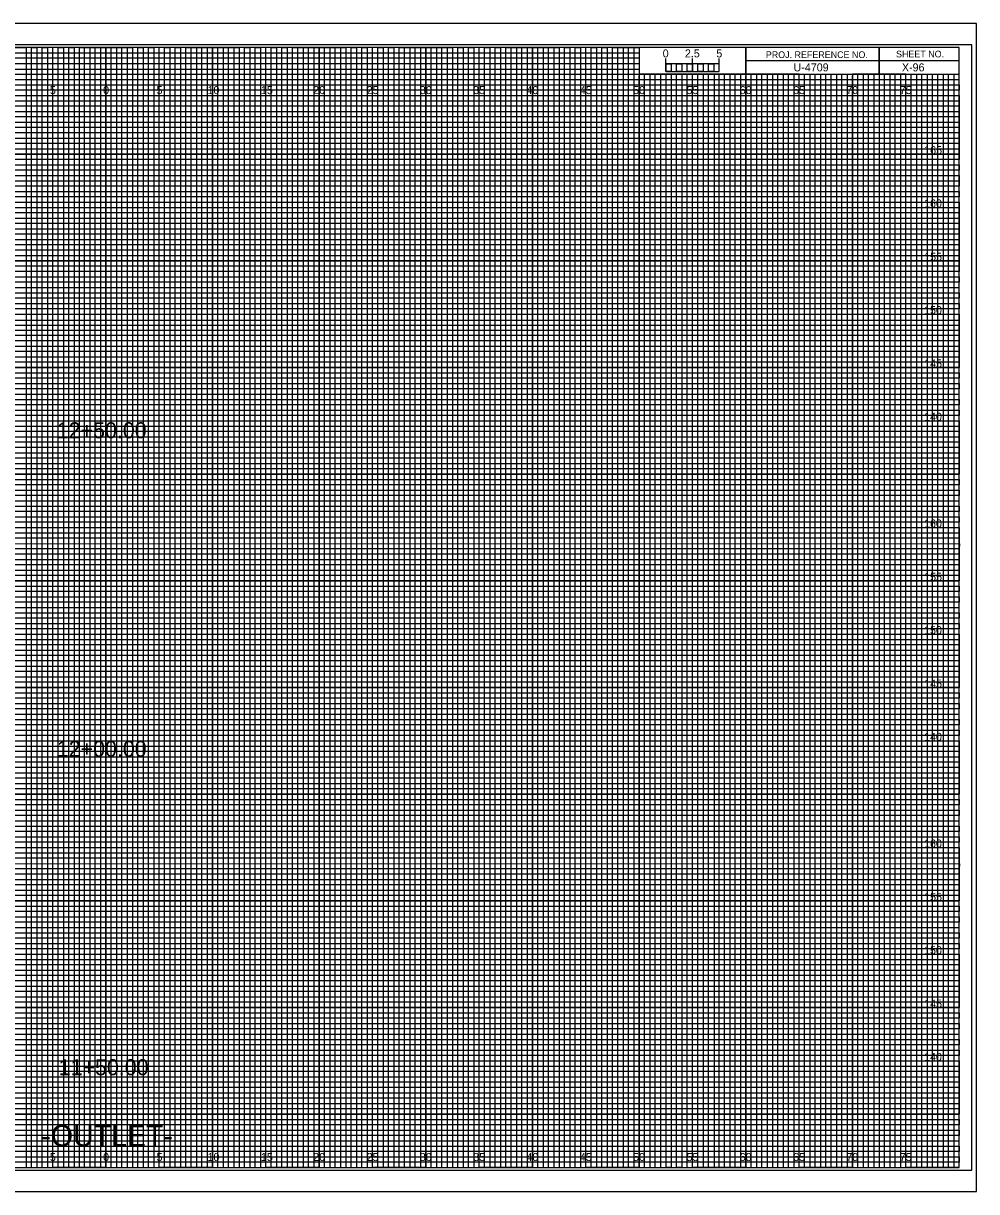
# Model space of a CAD drawing. Extents: x -7 to 162, y 108 to 217.
# Drawn here: x 72.2 to 161.7, y 107.7 to 217.2 of the extents above; entities that cross this region are included whole.
import ezdxf

# ---------------------------------------------------------------- set-up
doc = ezdxf.new("R2010")
doc.units = 0
for name, color, linetype in [('Exist CMT Pavement', 7, 'Continuous'), ('Exist Cross Section Cell', 7, 'Continuous'), ('Exist XS Center Line Elevation Label', 7, 'Continuous'), ('Exist XS Ground Line', 7, 'Continuous'), ('Prop CMT Concrete Structures', 7, 'Continuous'), ('Prop CMT Pvmt Course 1 CG', 7, 'Continuous'), ('Prop CMT Pvmt Course 1 Wedge', 7, 'Continuous'), ('Prop CMT Pvmt Course 2', 7, 'Continuous'), ('Prop CMT Pvmt Course 2 Wedge', 7, 'Continuous'), ('Prop CMT Pvmt Course 3', 7, 'Continuous'), ('Prop CMT Pvmt Course 3 Wedge', 7, 'Continuous'), ('Prop CMT Pvmt Surface', 7, 'Continuous'), ('Prop CMT Pvmt Wedge Surface 1', 7, 'Continuous'), ('Prop CMT Pvmt Wedge Surface 2', 7, 'Continuous'), ('Prop CMT Pvmt Wedge Surface 3', 7, 'Continuous'), ('Prop CMT Subgrade Earthwork', 7, 'Continuous'), ('Scratch_Level_0', 7, 'Continuous')]:
    doc.layers.add(name, color=color, linetype=linetype)

msp = doc.modelspace()

# ---------------------------------------------------------------- linework, layer by layer
at = {"layer": 'Exist XS Center Line Elevation Label'}
for points in [[(67.5, 215), (72.5, 215), (72.5, 110), (77.5, 110), (77.5, 215), (82.5, 215), (82.5, 110), (87.5, 110), (87.5, 215), (92.5, 215), (92.5, 110), (97.5, 110), (97.5, 215), (102.5, 215), (102.5, 110), (107.5, 110), (107.5, 215), (112.5, 215), (112.5, 110), (117.5, 110), (117.5, 215), (122.5, 215), (122.5, 110), (127.5, 110), (127.5, 215), (129.97, 215), (130, 215), (130, 212.5), (132.5, 212.5), (132.5, 110), (137.5, 110), (137.5, 212.5), (142.5, 212.5), (142.5, 110), (147.5, 110), (147.5, 212.5), (152.5, 212.5), (152.5, 110), (157.5, 110), (157.5, 212.5)], [(0, 212.5), (137.5, 212.5)], [(0, 202.5), (160, 202.5), (160, 207.5), (0, 207.5)], [(0, 192.5), (160, 192.5), (160, 197.5), (0, 197.5)], [(0, 182.5), (160, 182.5), (160, 187.5), (0, 187.5)], [(0, 172.5), (160, 172.5), (160, 177.5), (0, 177.5)], [(0, 162.5), (160, 162.5), (160, 167.5), (0, 167.5)], [(0, 152.5), (160, 152.5), (160, 157.5), (0, 157.5)], [(0, 142.5), (160, 142.5), (160, 147.5), (0, 147.5)], [(0, 132.5), (160, 132.5), (160, 137.5), (0, 137.5)], [(0, 122.5), (160, 122.5), (160, 127.5), (0, 127.5)], [(0, 112.5), (160, 112.5), (160, 117.5), (0, 117.5)]]:
    msp.add_lwpolyline(points, dxfattribs=at)
at = {"layer": 'Exist XS Ground Line'}
for p, q in [((75, 215), (70, 215)), ((75, 110), (75, 215)), ((85, 215), (80, 215)), ((80, 215), (80, 110)), ((85, 110), (85, 215)), ((95, 215), (90, 215)), ((90, 215), (90, 110)), ((95, 110), (95, 215)), ((105, 215), (100, 215)), ((100, 215), (100, 110)), ((105, 110), (105, 215)), ((115, 215), (110, 215)), ((110, 215), (110, 110)), ((115, 110), (115, 215)), ((125, 215), (120, 215)), ((120, 215), (120, 110)), ((125, 110), (125, 215)), ((130, 215), (130, 110)), ((135, 110), (135, 212.5)), ((145, 212.5), (140, 212.5)), ((140, 212.5), (140, 110)), ((145, 110), (145, 212.5)), ((155, 212.5), (150, 212.5)), ((150, 212.5), (150, 110)), ((155, 110), (155, 212.5)), ((80, 110), (75, 110)), ((90, 110), (85, 110)), ((100, 110), (95, 110)), ((110, 110), (105, 110)), ((120, 110), (115, 110)), ((130, 110), (125, 110)), ((140, 110), (135, 110)), ((150, 110), (145, 110)), ((160, 110), (155, 110)), ((160, 110), (160, 110))]:
    msp.add_line(p, q, dxfattribs=at)
for points in [[(0, 210), (160, 210), (160, 205), (0, 205)], [(0, 200), (160, 200), (160, 195), (0, 195)], [(0, 190), (160, 190), (160, 185), (0, 185)], [(0, 180), (160, 180), (160, 175), (0, 175)], [(0, 170), (160, 170), (160, 165), (0, 165)], [(0, 160), (160, 160), (160, 155), (0, 155)], [(0, 150), (160, 150), (160, 145), (0, 145)], [(0, 140), (160, 140), (160, 135), (0, 135)], [(0, 130), (160, 130), (160, 125), (0, 125)], [(0, 120), (160, 120), (160, 115), (0, 115)]]:
    msp.add_lwpolyline(points, dxfattribs=at)
at = {"layer": 'Prop CMT Concrete Structures'}
for p, q in [((161.65, 217.25), (-6.7, 217.25)), ((-6.7, 107.75), (161.65, 107.75))]:
    msp.add_line(p, q, dxfattribs=at)
at = {"layer": 'Prop CMT Pvmt Course 1 Wedge'}
msp.add_lwpolyline([(-6.7, 107.75), (161.65, 107.75), (161.65, 217.25), (-6.7, 217.25)], close=True, dxfattribs=at)
at = {"layer": 'Prop CMT Pvmt Course 2'}
for p, q in [((152.5, 215), (152.5, 212.5)), ((152.5, 212.5), (152.5, 215)), ((160, 213.75), (140, 213.75)), ((140, 213.75), (140, 212.5)), ((140, 212.5), (160, 212.5))]:
    msp.add_line(p, q, dxfattribs=at)
for points in [[(160, 215), (0, 215), (0, 110), (160, 110)], [(140, 215), (130, 215), (130, 212.52), (140, 212.52)], [(160, 215), (140, 215), (140, 212.5), (160, 212.5)]]:
    msp.add_lwpolyline(points, close=True, dxfattribs=at)
at = {"layer": 'Prop CMT Pvmt Course 2 Wedge'}
msp.add_lwpolyline([(-5.4, 109.75), (161.2, 109.75), (161.2, 215.25), (-5.4, 215.25)], close=True, dxfattribs=at)
at = {"layer": 'Prop CMT Pvmt Course 3'}
for p, q in [((133.5, 212.5), (133, 212.5)), ((133, 212.5), (133, 110)), ((133.5, 110), (133.5, 212.5)), ((134.5, 212.5), (134, 212.5)), ((134, 212.5), (134, 110)), ((134.5, 110), (134.5, 212.5)), ((133, 110), (132.5, 110)), ((134, 110), (133.5, 110))]:
    msp.add_line(p, q, dxfattribs=at)
for points in [[(72.5, 110), (73, 110), (73, 215), (73.5, 215), (73.5, 110)], [(73.5, 110), (74, 110), (74, 215), (74.5, 215), (74.5, 110)], [(75, 110), (75.5, 110), (75.5, 215), (76, 215), (76, 110)], [(76, 110), (76.5, 110), (76.5, 215), (77, 215), (77, 110)], [(77.5, 110), (78, 110), (78, 215), (78.5, 215), (78.5, 110)], [(78.5, 110), (79, 110), (79, 215), (79.5, 215), (79.5, 110)], [(80, 110), (80.5, 110), (80.5, 215), (81, 215), (81, 110)], [(81, 110), (81.5, 110), (81.5, 215), (82, 215), (82, 110)], [(82.5, 110), (83, 110), (83, 215), (83.5, 215), (83.5, 110)], [(83.5, 110), (84, 110), (84, 215), (84.5, 215), (84.5, 110)], [(85, 110), (85.5, 110), (85.5, 215), (86, 215), (86, 110)], [(86, 110), (86.5, 110), (86.5, 215), (87, 215), (87, 110)], [(87.5, 110), (88, 110), (88, 215), (88.5, 215), (88.5, 110)], [(88.5, 110), (89, 110), (89, 215), (89.5, 215), (89.5, 110)], [(90, 110), (90.5, 110), (90.5, 215), (91, 215), (91, 110)], [(91, 110), (91.5, 110), (91.5, 215), (92, 215), (92, 110)], [(92.5, 110), (93, 110), (93, 215), (93.5, 215), (93.5, 110)], [(93.5, 110), (94, 110), (94, 215), (94.5, 215), (94.5, 110)], [(95, 110), (95.5, 110), (95.5, 215), (96, 215), (96, 110)], [(96, 110), (96.5, 110), (96.5, 215), (97, 215), (97, 110)], [(97.5, 110), (98, 110), (98, 215), (98.5, 215), (98.5, 110)], [(98.5, 110), (99, 110), (99, 215), (99.5, 215), (99.5, 110)], [(100, 110), (100.5, 110), (100.5, 215), (101, 215), (101, 110)], [(101, 110), (101.5, 110), (101.5, 215), (102, 215), (102, 110)], [(102.5, 110), (103, 110), (103, 215), (103.5, 215), (103.5, 110)], [(103.5, 110), (104, 110), (104, 215), (104.5, 215), (104.5, 110)], [(105, 110), (105.5, 110), (105.5, 215), (106, 215), (106, 110)], [(106, 110), (106.5, 110), (106.5, 215), (107, 215), (107, 110)], [(107.5, 110), (108, 110), (108, 215), (108.5, 215), (108.5, 110)], [(108.5, 110), (109, 110), (109, 215), (109.5, 215), (109.5, 110)], [(110, 110), (110.5, 110), (110.5, 215), (111, 215), (111, 110)], [(111, 110), (111.5, 110), (111.5, 215), (112, 215), (112, 110)], [(112.5, 110), (113, 110), (113, 215), (113.5, 215), (113.5, 110)], [(113.5, 110), (114, 110), (114, 215), (114.5, 215), (114.5, 110)], [(115, 110), (115.5, 110), (115.5, 215), (116, 215), (116, 110)], [(116, 110), (116.5, 110), (116.5, 215), (117, 215), (117, 110)], [(117.5, 110), (118, 110), (118, 215), (118.5, 215), (118.5, 110)], [(118.5, 110), (119, 110), (119, 215), (119.5, 215), (119.5, 110)], [(120, 110), (120.5, 110), (120.5, 215), (121, 215), (121, 110)], [(121, 110), (121.5, 110), (121.5, 215), (122, 215), (122, 110)], [(122.5, 110), (123, 110), (123, 215), (123.5, 215), (123.5, 110)], [(123.5, 110), (124, 110), (124, 215), (124.5, 215), (124.5, 110)], [(125, 110), (125.5, 110), (125.5, 215), (126, 215), (126, 110)], [(126, 110), (126.5, 110), (126.5, 215), (127, 215), (127, 110)], [(127.5, 110), (128, 110), (128, 215), (128.5, 215), (128.5, 110)], [(128.5, 110), (129, 110), (129, 215), (129.5, 215), (129.5, 110)], [(130, 110), (130.5, 110), (130.5, 212.5), (131.01, 212.5), (131.01, 110)], [(131, 110), (131.5, 110), (131.5, 212.5), (132, 212.5), (132, 110)], [(135, 110), (135.49, 110), (135.49, 212.5), (136, 212.5), (136, 110)], [(136, 110), (136.5, 110), (136.5, 212.5), (137.03, 212.5), (137.03, 110)], [(137.5, 110), (138, 110), (138, 212.5), (138.5, 212.5), (138.5, 110)], [(138.5, 110), (139, 110), (139, 212.5), (139.5, 212.5), (139.5, 110)], [(140, 110), (140.5, 110), (140.5, 212.5), (141, 212.5), (141, 110)], [(141, 110), (141.5, 110), (141.5, 212.5), (142, 212.5), (142, 110)], [(142.5, 110), (143, 110), (143, 212.5), (143.5, 212.5), (143.5, 110)], [(143.5, 110), (144, 110), (144, 212.5), (144.5, 212.5), (144.5, 110)], [(145, 110), (145.5, 110), (145.5, 212.5), (146, 212.5), (146, 110)], [(146, 110), (146.5, 110), (146.5, 212.5), (147, 212.5), (147, 110)], [(147.5, 110), (148, 110), (148, 212.5), (148.5, 212.5), (148.5, 110)], [(148.5, 110), (149, 110), (149, 212.5), (149.5, 212.5), (149.5, 110)], [(150, 110), (150.5, 110), (150.5, 212.5), (151, 212.5), (151, 110)], [(151, 110), (151.5, 110), (151.5, 212.5), (152, 212.5), (152, 110)], [(152.5, 110), (153, 110), (153, 212.5), (153.5, 212.5), (153.5, 110)], [(153.5, 110), (154, 110), (154, 212.5), (154.5, 212.5), (154.5, 110)], [(155, 110), (155.5, 110), (155.5, 212.5), (156, 212.5), (156, 110)], [(156, 110), (156.5, 110), (156.5, 212.5), (157, 212.5), (157, 110)], [(157.5, 110), (158, 110), (158, 212.5), (158.5, 212.5), (158.5, 110)], [(158.5, 110), (159, 110), (159, 212.5), (159.5, 212.5), (159.5, 110)]]:
    msp.add_lwpolyline(points, dxfattribs=at)
at = {"layer": 'Prop CMT Pvmt Course 3 Wedge'}
for p, q in [((75, 110), (75, 215)), ((80, 110), (80, 215)), ((85, 110), (85, 215)), ((90, 110), (90, 215)), ((95, 110), (95, 215)), ((100, 110), (100, 215)), ((105, 110), (105, 215)), ((110, 110), (110, 215)), ((115, 110), (115, 215)), ((120, 110), (120, 215)), ((125, 110), (125, 215)), ((130, 110), (130, 212.34)), ((135, 110), (135, 212.34)), ((140, 110), (140, 212.34)), ((145, 110), (145, 212.34)), ((150, 110), (150, 212.34)), ((155, 110), (155, 212.34)), ((0, 210), (160, 210)), ((0, 205), (160, 205)), ((0, 200), (160, 200)), ((0, 195), (160, 195)), ((0, 190), (160, 190)), ((0, 185), (160, 185)), ((0, 180), (160, 180)), ((0, 175), (160, 175)), ((0, 170), (160, 170)), ((0, 165), (160, 165)), ((0, 160), (160, 160)), ((0, 155), (160, 155)), ((0, 150), (160, 150)), ((0, 145), (160, 145)), ((0, 140), (160, 140)), ((0, 135), (160, 135)), ((0, 130), (160, 130)), ((0, 125), (160, 125)), ((0, 120), (160, 120)), ((0, 115), (160, 115))]:
    msp.add_line(p, q, dxfattribs=at)
at = {"layer": 'Prop CMT Subgrade Earthwork'}
for p, q in [((132.5, 212.75), (132.5, 213.95)), ((132.5, 213.45), (132.5, 213.95)), ((135, 212.75), (135, 213.95)), ((137.5, 212.75), (137.5, 213.95)), ((137.5, 213.45), (137.5, 213.95))]:
    msp.add_line(p, q, dxfattribs=at)
for points in [[(137.5, 213.45), (132.5, 213.45), (132.5, 212.75), (137.5, 212.75)], [(132.5, 213.45), (133, 213.45), (133, 212.75), (132.5, 212.75)], [(133.5, 213.45), (134, 213.45), (134, 212.75), (133.5, 212.75)], [(134.5, 213.45), (135, 213.45), (135, 212.75), (134.5, 212.75)], [(135.5, 213.45), (136, 213.45), (136, 212.75), (135.5, 212.75)], [(136.5, 213.45), (137, 213.45), (137, 212.75), (136.5, 212.75)]]:
    msp.add_lwpolyline(points, close=True, dxfattribs=at)
at = {"layer": 'Scratch_Level_0'}
for p, q in [((0, 214.5), (130, 214.5)), ((130, 213.99), (0, 213.99)), ((130, 214.5), (130, 213.99)), ((0, 213.5), (130, 213.5)), ((130, 212.94), (0, 212.94)), ((130, 213.5), (130, 212.94)), ((0, 212), (160, 212))]:
    msp.add_line(p, q, dxfattribs=at)
for points in [[(0, 211.5), (135, 211.5), (160, 211.5), (160, 211), (0, 211)], [(0, 210.5), (160, 210.5), (160, 209.5), (0, 209.5)], [(0, 209), (160, 209), (160, 208.5), (0, 208.49)], [(0, 208), (160, 208), (160, 207), (0, 207)], [(0, 206.5), (160, 206.5), (160, 206), (0, 206)], [(0, 205.5), (160, 205.5), (160, 204.5), (0, 204.5)], [(0, 204), (160, 204), (160, 203.5), (0, 203.5)], [(0, 203), (160, 203), (160, 202), (0, 202)], [(0, 201.5), (160, 201.5), (160, 201), (0, 201)], [(0, 200.5), (160, 200.5), (160, 199.5), (0, 199.5)], [(0, 199), (160, 199), (160, 198.5), (0, 198.5)], [(0, 198), (160, 198), (160, 196.97), (160, 196.5), (160, 196), (0, 196)], [(0, 197), (160, 197), (160, 196.5), (0, 196.5)], [(0, 195.5), (160, 195.5), (160, 194.5), (0, 194.52)], [(0, 194.52), (160, 194.5), (160, 194), (0, 194)], [(0, 193.5), (160, 193.5), (160, 193), (0, 193)], [(0, 192), (160, 192), (160, 191.5), (0, 191.5)], [(0, 191), (160, 191), (160, 190.5), (0, 190.5)], [(-0.04, 189.44), (160, 189.44), (160, 188.94), (-0.04, 188.94)], [(0, 188.5), (160, 188.5), (160, 188), (0, 188)], [(0, 187), (160, 187), (160, 186.5), (0, 186.5)], [(0, 186), (160, 186), (160, 185.5), (0, 185.5)], [(0, 184.5), (160, 184.5), (160, 184), (0, 184)], [(0, 183.5), (160, 183.5), (160, 183), (0, 183)], [(0, 182), (160, 182), (160, 181.5), (0, 181.5)], [(0, 181), (160, 181), (160, 180.5), (0, 180.5)], [(0, 179.5), (160, 179.5), (160, 178.99), (0, 179)], [(0, 178.5), (160, 178.5), (160, 178), (0, 178)], [(0, 177), (160, 177), (160, 176.5), (0, 176.5)], [(0, 176), (160, 176), (160, 175.5), (0, 175.5)], [(0, 174.5), (160, 174.5), (160, 174), (0, 174)], [(0, 173.5), (160, 173.5), (160, 173), (0, 173)], [(0, 172), (160, 172), (160, 171.5), (0, 171.5)], [(0, 171), (160, 171), (160, 170.5), (0, 170.5)], [(0, 169.5), (160, 169.5), (160, 169), (0, 169)], [(0, 168.5), (160.03, 168.46), (160, 168), (0, 168)], [(0, 167), (160, 167), (160, 166.5), (0, 166.5)], [(0, 166), (160, 166), (160, 165.5), (0, 165.5)], [(0, 164.5), (160, 164.5), (160, 164), (0, 164)], [(0, 163.5), (160, 163.5), (160, 163), (0, 163)], [(0, 162), (160, 162), (160, 161.5), (0, 161.5)], [(0, 161), (160, 161), (160, 160.5), (0, 160.5)], [(0, 159.5), (160, 159.5), (160, 159), (0, 159)], [(0, 158.5), (160, 158.5), (160, 158), (0, 158)], [(0, 157), (160, 157), (160, 156.5), (0, 156.5)], [(0, 156), (160, 156), (160, 155.5), (0, 155.5)], [(0, 154.5), (160, 154.5), (160, 154), (0, 154)], [(0, 153.5), (160, 153.5), (160, 153), (0, 153)], [(0, 152), (160, 152), (160, 151.5), (0, 151.5)], [(0, 151), (160, 151), (160, 150.5), (0, 150.5)], [(0, 149.5), (160, 149.5), (160, 148.99), (0, 149)], [(0, 148.5), (160, 148.5), (160, 148), (0, 148)], [(0, 147), (160, 147), (160, 146.5), (0, 146.5)], [(0, 146), (160, 146), (160, 145.5), (0, 145.5)], [(0, 144.5), (160, 144.5), (160, 144), (0, 144)], [(0, 143.5), (160, 143.5), (160, 143), (0, 143)], [(0, 142), (160, 142), (160, 141.5), (0, 141.5)], [(0, 141), (160, 141), (160, 140.5), (0, 140.5)], [(0, 139.5), (160, 139.5), (160, 139), (0, 139)], [(0, 138.5), (160.03, 138.46), (160, 138), (0, 138)], [(0, 137), (160, 137), (160, 136.5), (0, 136.5)], [(0, 136), (160, 136), (160, 135.5), (0, 135.5)], [(0, 134.5), (160, 134.5), (160, 134), (0, 134)], [(0, 133.5), (160, 133.5), (160, 133), (0, 133)], [(0, 132), (160, 132), (160, 131.5), (0, 131.5)], [(0, 131), (160, 131), (160, 130.5), (0, 130.5)], [(0, 129.5), (160, 129.5), (160, 129), (0, 129)], [(0, 128.5), (160, 128.5), (160, 128), (0, 128)], [(0, 127), (160, 127), (160, 126.5), (0, 126.5)], [(0, 126), (160, 126), (160, 125.5), (0, 125.5)], [(0, 124.5), (160, 124.5), (160, 124), (0, 124)], [(0, 123.5), (160, 123.5), (160, 123), (0, 123)], [(0, 122), (160, 122), (160, 121.5), (0, 121.5)], [(0, 121), (160, 121), (160, 120.5), (0, 120.5)], [(0, 119.5), (160, 119.5), (160, 119), (0, 119)], [(0, 118.5), (160, 118.5), (160, 118), (0, 118)], [(0, 117), (160, 117), (160, 116.5), (0, 116.5)], [(0, 116), (160, 116), (160, 115.5), (0, 115.5)], [(0, 114.5), (160, 114.5), (160, 114), (0, 114)], [(0, 113.5), (160, 113.5), (160, 113), (0, 113)], [(0, 112), (160, 112), (160, 111.5), (0, 111.5)], [(0, 111), (160, 111), (160, 110.5), (0, 110.5)]]:
    msp.add_lwpolyline(points, dxfattribs=at)

# ---------------------------------------------------------------- texts
at = {"layer": 'Exist CMT Pavement'}
for s, p in [('165', (156.73, 205)), ('160', (156.72, 200)), ('155', (156.73, 195)), ('150', (156.72, 190)), ('145', (156.73, 185)), ('140', (156.72, 180)), ('160', (156.72, 170)), ('155', (156.73, 165)), ('150', (156.72, 160)), ('145', (156.73, 155)), ('140', (156.72, 150)), ('160', (156.72, 140)), ('155', (156.73, 135)), ('150', (156.72, 130)), ('145', (156.73, 125)), ('140', (156.72, 120))]:
    msp.add_text(s, height=0.75, dxfattribs=at).set_placement(p)
at = {"layer": 'Exist Cross Section Cell'}
for s, p in [('5', (74.74, 210.62)), ('0', (79.73, 210.62)), ('0', (79.73, 210.62)), ('5', (84.74, 210.62)), ('10', (89.52, 210.62)), ('15', (94.53, 210.62)), ('20', (99.43, 210.62)), ('25', (104.44, 210.62)), ('30', (109.43, 210.62)), ('35', (114.44, 210.62)), ('40', (119.43, 210.62)), ('45', (124.44, 210.62)), ('50', (129.43, 210.62)), ('55', (134.44, 210.62)), ('60', (139.43, 210.62)), ('65', (144.44, 210.62)), ('70', (149.43, 210.62)), ('75', (154.44, 210.62)), ('5', (74.74, 110.62)), ('0', (79.73, 110.62)), ('0', (79.73, 110.62)), ('5', (84.74, 110.62)), ('10', (89.52, 110.62)), ('15', (94.53, 110.62)), ('20', (99.43, 110.62)), ('25', (104.44, 110.62)), ('30', (109.43, 110.62)), ('35', (114.44, 110.62)), ('40', (119.43, 110.62)), ('45', (124.44, 110.62)), ('50', (129.43, 110.62)), ('55', (134.44, 110.62)), ('60', (139.43, 110.62)), ('65', (144.44, 110.62)), ('70', (149.43, 110.62)), ('75', (154.44, 110.62))]:
    msp.add_text(s, height=0.75, dxfattribs=at).set_placement(p)
at = {"layer": 'Prop CMT Pvmt Course 1 CG'}
msp.add_text('X-96', height=0.75, dxfattribs=at).set_placement((154.64, 212.75))
at = {"layer": 'Prop CMT Pvmt Course 2'}
for s, p in [('PROJ. REFERENCE NO.', (141.88, 214)), ('SHEET NO.', (154.09, 214.06))]:
    msp.add_text(s, height=0.625, dxfattribs=at).set_placement(p)
at = {"layer": 'Prop CMT Pvmt Surface'}
for s, p in [('12+50.00', (75.39, 178.36)), ('12+00.00', (75.39, 148.51)), ('11+50.00', (75.57, 118.66))]:
    msp.add_text(s, height=1.5, dxfattribs=at).set_placement(p)
at = {"layer": 'Prop CMT Pvmt Wedge Surface 1'}
msp.add_text('U-4709', height=0.75, dxfattribs=at).set_placement((144.48, 212.75))
at = {"layer": 'Prop CMT Pvmt Wedge Surface 2'}
msp.add_text('-OUTLET-', height=2, dxfattribs=at).set_placement((73.94, 112))
at = {"layer": 'Prop CMT Pvmt Wedge Surface 3'}
for s, p in [('2.5', (134.29, 214.06)), ('5', (137.24, 214.06))]:
    msp.add_text(s, height=0.75, dxfattribs=at).set_placement(p)
at = {"layer": 'Prop CMT Subgrade Earthwork'}
msp.add_text('0', height=0.75, dxfattribs=at).set_placement((132.21, 214.06))

doc.saveas('drawing.dxf')
